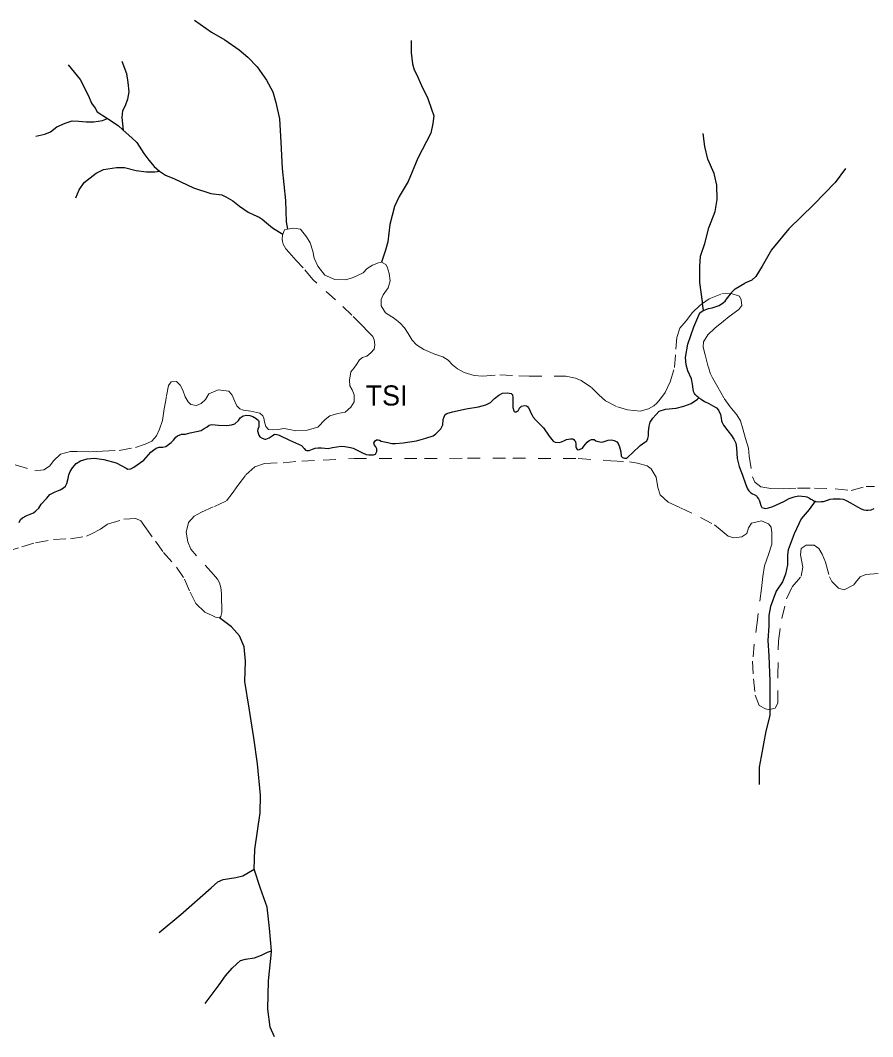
# Model space of a CAD drawing. Extents: x 391.8 to 446, y 8452 to 8507.5.
# Drawn here: x 410.75 to 417.52, y 8495.53 to 8503.6 of the extents above; entities that cross this region are included whole.
import ezdxf
from ezdxf.enums import TextEntityAlignment as Align

# ---------------------------------------------------------------- set-up
doc = ezdxf.new("R2010")
doc.units = 0
doc.header["$LTSCALE"] = 0.064
doc.linetypes.add('LONG_DASHED', pattern=[7.5, 6, -1.5])
doc.linetypes.add('SHORT_DASHED', pattern=[2.7, 1.5, -1.2])
for name, color, linetype, lineweight in [('21', 7, 'SHORT_DASHED', 13), ('7', 7, 'Continuous', 25), ('9', 7, 'LONG_DASHED', 25)]:
    doc.layers.add(name, color=color, linetype=linetype, lineweight=lineweight)
doc.layers.add('61', color=7, linetype='Continuous')

msp = doc.modelspace()

# ---------------------------------------------------------------- linework, layer by layer
at = {"layer": '21'}
for points in [[(412.471, 8500.5378), (412.4932, 8500.512), (412.5227, 8500.501), (412.5818, 8500.4936), (412.6519, 8500.4788), (412.6778, 8500.4567), (412.6852, 8500.4383), (412.6888, 8500.4088), (412.6999, 8500.3719), (412.7221, 8500.3498), (412.7516, 8500.3461), (412.7996, 8500.3498), (412.8439, 8500.3572), (412.8919, 8500.3498), (412.9362, 8500.3387), (413.0285, 8500.3424), (413.1134, 8500.3682), (413.1725, 8500.4272), (413.2094, 8500.4567), (413.2722, 8500.4751), (413.3312, 8500.4862), (413.3755, 8500.5268), (413.4014, 8500.5673), (413.4014, 8500.6226), (413.3866, 8500.6632), (413.3682, 8500.6964), (413.3645, 8500.7406), (413.3768, 8500.8061), (413.4027, 8500.8393), (413.4211, 8500.8651), (413.4433, 8500.9019), (413.4691, 8500.9204), (413.5023, 8500.9314), (413.5356, 8500.9572), (413.5614, 8500.9867), (413.5651, 8501.0199), (413.5614, 8501.0605), (413.5503, 8501.0863), (413.5134, 8501.1232), (413.4654, 8501.1748), (413.3842, 8501.2559), (413.255, 8501.3776), (413.0741, 8501.5398), (412.9965, 8501.632), (412.9412, 8501.691), (412.8858, 8501.7537), (412.8599, 8501.7832), (412.8378, 8501.82), (412.8341, 8501.8422), (412.8304, 8501.8606), (412.833, 8501.8925), (412.833, 8501.8926), (412.8359, 8501.9004)], [(412.8359, 8501.9004), (412.8481, 8501.9334), (412.8727, 8501.9382)], [(412.8727, 8501.9382), (412.9239, 8501.9482), (412.9747, 8501.9388), (413.0222, 8501.8794), (413.0519, 8501.8311), (413.0741, 8501.7647), (413.0852, 8501.7094), (413.1147, 8501.6467), (413.1701, 8501.573), (413.2476, 8501.5398), (413.3362, 8501.5361), (413.3953, 8501.5546), (413.4728, 8501.5914), (413.506, 8501.6283), (413.5466, 8501.6541), (413.5946, 8501.6725), (413.6204, 8501.677)], [(413.6204, 8501.677), (413.6537, 8501.6578), (413.6648, 8501.6394), (413.6796, 8501.5877), (413.6869, 8501.5288), (413.6722, 8501.4734), (413.6316, 8501.4181), (413.6168, 8501.3813), (413.6168, 8501.3296), (413.65, 8501.2743), (413.7239, 8501.2301), (413.7682, 8501.1932), (413.8014, 8501.1564), (413.8309, 8501.1121), (413.8642, 8501.0568), (413.8974, 8501.0199), (413.9565, 8500.9831), (414.0502, 8500.9444), (414.1056, 8500.9259), (414.1499, 8500.9001), (414.1831, 8500.8632), (414.2237, 8500.8301), (414.2754, 8500.8006), (414.3566, 8500.7784), (414.4231, 8500.7711), (414.5597, 8500.7821), (414.711, 8500.7748)], [(416.1704, 8501.3483), (416.2232, 8501.3851), (416.3229, 8501.4256), (416.3948, 8501.4292)], [(416.3948, 8501.4292), (416.3967, 8501.4293), (416.4632, 8501.4072), (416.4779, 8501.3777), (416.4816, 8501.3335), (416.4595, 8501.3003), (416.3819, 8501.245), (416.3376, 8501.2081), (416.2675, 8501.1528), (416.2121, 8501.1012), (416.1789, 8501.0459), (416.1752, 8501.0016), (416.19, 8500.9426), (416.2164, 8500.8445), (416.2311, 8500.7966), (416.2496, 8500.7597), (416.2902, 8500.686), (416.3419, 8500.5938), (416.3899, 8500.5274), (416.4416, 8500.4647), (416.4711, 8500.4168), (416.4896, 8500.3541), (416.5117, 8500.2767), (416.5339, 8500.1993), (416.5412, 8500.1366), (416.5676, 8499.9719), (416.586, 8499.9314), (416.634, 8499.8945), (416.7115, 8499.8797), (416.8112, 8499.8761), (416.9257, 8499.8834), (417.0586, 8499.8834), (417.2247, 8499.8761), (417.3502, 8499.865), (417.4697, 8499.8953), (417.5362, 8499.8953)], [(415.346, 8500.6236), (415.3977, 8500.5756), (415.4937, 8500.5277), (415.575, 8500.5056), (415.6746, 8500.4945), (415.7411, 8500.513), (415.7838, 8500.5358), (415.8059, 8500.558), (415.8354, 8500.5911), (415.8724, 8500.6428), (415.913, 8500.7276), (415.9462, 8500.8419), (415.9573, 8500.9857), (415.9647, 8501.0779), (415.9906, 8501.1528), (416.0386, 8501.2118), (416.0903, 8501.2782), (416.1493, 8501.3335), (416.1704, 8501.3483)], [(414.711, 8500.7748), (414.7923, 8500.7711), (415.0839, 8500.7711), (415.1615, 8500.7563), (415.2058, 8500.7379), (415.2907, 8500.6789), (415.346, 8500.6236)], [(410.7101, 8500.0678), (410.8651, 8500.0191), (410.937, 8500.0272), (410.9821, 8500.0572), (411.0168, 8500.1011), (411.0684, 8500.1527), (411.1497, 8500.1748), (411.2013, 8500.1748), (411.3066, 8500.172), (411.4026, 8500.1757), (411.5355, 8500.1831), (411.6647, 8500.2052), (411.7422, 8500.231), (411.7939, 8500.2568), (411.8308, 8500.2974), (411.8568, 8500.3509), (411.879, 8500.421), (411.8937, 8500.5131), (411.9122, 8500.6164), (411.9269, 8500.6975), (411.9491, 8500.727), (411.9897, 8500.7307), (412.0192, 8500.7012), (412.0414, 8500.6606), (412.0599, 8500.609), (412.082, 8500.5684), (412.1042, 8500.5463), (412.1485, 8500.539), (412.1854, 8500.5537), (412.2223, 8500.5869)], [(412.2223, 8500.5869), (412.2481, 8500.6311), (412.322, 8500.6643), (412.4069, 8500.6533), (412.4327, 8500.6201), (412.4549, 8500.5721), (412.471, 8500.5378)], [(412.3323, 8498.8529), (412.3427, 8498.8643), (412.3502, 8498.8943), (412.3502, 8498.9411), (412.3483, 8498.9955), (412.3483, 8499.0442), (412.3427, 8499.0947), (412.3314, 8499.1303), (412.3164, 8499.1603), (412.2845, 8499.1978), (412.1506, 8499.3464), (412.1056, 8499.3978), (412.0799, 8499.4556), (412.067, 8499.5326), (412.0863, 8499.6097), (412.1313, 8499.661), (412.1892, 8499.6931), (412.292, 8499.7381), (412.3884, 8499.783), (412.4334, 8499.8408), (412.4784, 8499.905), (412.5427, 8499.9884), (412.6134, 8500.0526), (412.6906, 8500.0783), (412.8384, 8500.0847), (412.9863, 8500.0976), (413.1568, 8500.1054), (413.4011, 8500.1183), (413.9603, 8500.1183), (414.3039, 8500.1203), (414.6637, 8500.1203), (415.1817, 8500.1183), (415.4416, 8500.0994), (415.5894, 8500.093), (415.6537, 8500.0801), (415.7308, 8500.0609), (415.763, 8500.0352), (415.8015, 8499.971), (415.8144, 8499.8875), (415.8337, 8499.8298), (415.898, 8499.772), (415.9944, 8499.727), (416.1551, 8499.65), (416.2644, 8499.5922), (416.3094, 8499.5537), (416.3737, 8499.5023), (416.4187, 8499.4895), (416.4829, 8499.4959), (416.5215, 8499.5216), (416.5344, 8499.5665), (416.5601, 8499.6051), (416.6372, 8499.6243), (416.6951, 8499.5986), (416.7144, 8499.573), (416.7208, 8499.528), (416.7208, 8499.4381), (416.6951, 8499.3547), (416.6629, 8499.2648), (416.6501, 8499.1813), (416.6372, 8499.085), (416.6065, 8498.8362), (416.5808, 8498.6436), (416.5679, 8498.5088), (416.5743, 8498.3675), (416.5872, 8498.2391)], [(410.6399, 8499.3785), (410.7621, 8499.4171), (410.8713, 8499.4492), (411.0128, 8499.4748), (411.1478, 8499.4813), (411.2763, 8499.5005), (411.3149, 8499.5198), (411.3856, 8499.5583), (411.4435, 8499.5968), (411.572, 8499.6353), (411.6685, 8499.6418), (411.707, 8499.6225), (411.7392, 8499.5776), (411.8227, 8499.462), (411.887, 8499.3721), (411.9899, 8499.2566), (412.0542, 8499.1603), (412.0992, 8499.0575), (412.1442, 8498.9677), (412.2149, 8498.897), (412.2727, 8498.8714), (412.3052, 8498.8568), (412.3323, 8498.8529)], [(416.7672, 8498.1749), (416.7672, 8498.3996), (416.7736, 8498.6693), (416.7993, 8498.849), (416.8379, 8499.0031), (416.8829, 8499.0994), (416.9536, 8499.1829), (416.9666, 8499.2558), (416.9473, 8499.3521), (416.9537, 8499.4035), (416.9923, 8499.4292), (417.0566, 8499.4292), (417.0951, 8499.4035), (417.1209, 8499.3586), (417.1466, 8499.2944), (417.1787, 8499.1788), (417.198, 8499.1403), (417.2494, 8499.0889), (417.2944, 8499.0761), (417.3716, 8499.1146), (417.3844, 8499.1339), (417.423, 8499.1788), (417.468, 8499.1981), (417.5644, 8499.2045)], [(416.5872, 8498.2391), (416.6193, 8498.1557), (416.6708, 8498.13), (416.7029, 8498.1236), (416.7051, 8498.1242)], [(416.7051, 8498.1242), (416.7479, 8498.1364), (416.7672, 8498.1749)]]:
    msp.add_lwpolyline(points, dxfattribs=at)
at = {"layer": '7'}
for points in [[(416.3948, 8501.4292), (416.3986, 8501.4349), (416.4284, 8501.4647), (416.5067, 8501.5093)], [(416.1769, 8501.2941), (416.2161, 8501.3084), (416.2459, 8501.3158), (416.3018, 8501.3344), (416.3353, 8501.3568), (416.3502, 8501.3679), (416.3688, 8501.394), (416.3837, 8501.4126), (416.3948, 8501.4292)], [(416.1417, 8500.6005), (416.1286, 8500.6118), (416.1182, 8500.6192), (416.1123, 8500.6266), (416.1049, 8500.6355), (416.099, 8500.6503), (416.0945, 8500.668), (416.0895, 8500.7095), (416.082, 8500.7504), (416.0522, 8500.8136), (416.0411, 8500.862), (416.0336, 8500.9215), (416.0522, 8501.0257), (416.1007, 8501.1633), (416.1491, 8501.2749), (416.1751, 8501.2935), (416.1769, 8501.2941)], [(413.0167, 8500.1853), (413.0263, 8500.1829), (413.0455, 8500.1829), (413.0719, 8500.1925), (413.0911, 8500.1997), (413.1151, 8500.2021), (413.1415, 8500.2021), (413.1703, 8500.1997), (413.1967, 8500.1973), (413.2303, 8500.2069), (413.2639, 8500.2117), (413.2999, 8500.2165), (413.3287, 8500.2141), (413.3719, 8500.2069), (413.3935, 8500.1997), (413.4319, 8500.1829), (413.4679, 8500.1637), (413.4967, 8500.1494), (413.5183, 8500.147), (413.5566, 8500.147), (413.571, 8500.1518), (413.583, 8500.1733), (413.583, 8500.1949), (413.5734, 8500.2117), (413.5638, 8500.2237), (413.559, 8500.2428), (413.5686, 8500.2596), (413.5806, 8500.2668), (413.5926, 8500.2668), (413.6046, 8500.2644), (413.6166, 8500.2572), (413.6707, 8500.2453), (413.7019, 8500.2381), (413.7306, 8500.2381), (413.7906, 8500.2429), (413.8962, 8500.2596), (413.9706, 8500.2788), (414.0306, 8500.298), (414.0498, 8500.3148), (414.0906, 8500.3531), (414.1074, 8500.3866), (414.1098, 8500.4274), (414.1175, 8500.4502), (414.1247, 8500.4669), (414.1391, 8500.4765), (414.1847, 8500.4885), (414.2927, 8500.5125), (414.3911, 8500.5293), (414.4487, 8500.5436), (414.4847, 8500.5628), (414.5159, 8500.594), (414.5519, 8500.6203), (414.5807, 8500.6371), (414.6167, 8500.6395), (414.6503, 8500.6347), (414.6599, 8500.6227), (414.6623, 8500.6036), (414.6623, 8500.5245), (414.6695, 8500.4981), (414.6743, 8500.4909), (414.6791, 8500.4885), (414.6887, 8500.4885), (414.6983, 8500.4933), (414.7055, 8500.4981), (414.7103, 8500.5077), (414.7175, 8500.5221), (414.7271, 8500.5293), (414.7318, 8500.5341), (414.7558, 8500.5388), (414.7702, 8500.5364), (414.7798, 8500.5317), (414.787, 8500.5197), (414.7966, 8500.5029), (414.8038, 8500.4861), (414.8158, 8500.4622), (414.8254, 8500.4454), (414.8446, 8500.4238), (414.907, 8500.3615), (414.9526, 8500.2968), (414.9727, 8500.2693), (414.9822, 8500.2549), (414.999, 8500.2477), (415.0302, 8500.2453), (415.0494, 8500.2501), (415.0734, 8500.2621), (415.0902, 8500.2693), (415.1214, 8500.2741), (415.1382, 8500.2741), (415.1478, 8500.2693), (415.1526, 8500.2621), (415.1598, 8500.2525), (415.1622, 8500.2334), (415.1646, 8500.2118), (415.167, 8500.2022), (415.1742, 8500.1902)], [(415.2534, 8500.2477), (415.2702, 8500.2621), (415.287, 8500.2693), (415.3086, 8500.2693), (415.323, 8500.2597), (415.3446, 8500.2525), (415.3638, 8500.2477), (415.3806, 8500.2501), (415.4046, 8500.2597), (415.4214, 8500.2645), (415.4454, 8500.2669), (415.467, 8500.2621), (415.4886, 8500.2501), (415.5006, 8500.2382), (415.5102, 8500.2118), (415.5198, 8500.1711), (415.5246, 8500.1375), (415.5342, 8500.1255), (415.551, 8500.1207), (415.5678, 8500.1207), (415.5798, 8500.1303), (415.6134, 8500.1639), (415.6734, 8500.2214), (415.7118, 8500.2477), (415.7286, 8500.2573), (415.7358, 8500.2765), (415.7406, 8500.2981), (415.7406, 8500.3292), (415.7454, 8500.3748), (415.755, 8500.4059), (415.7742, 8500.4395), (415.7982, 8500.4658), (415.8258, 8500.4951), (415.8762, 8500.5095), (415.9602, 8500.5167), (416.0202, 8500.5335), (416.0801, 8500.555), (416.1305, 8500.5886), (416.1417, 8500.6005)], [(416.1417, 8500.6005), (416.1583, 8500.5881), (416.1849, 8500.5703), (416.219, 8500.5541), (416.2576, 8500.5348), (416.2798, 8500.52), (416.2976, 8500.5008), (416.3139, 8500.4682), (416.3186, 8500.4373), (416.3201, 8500.4181), (416.326, 8500.4033), (416.3378, 8500.3826), (416.3705, 8500.3382), (416.4001, 8500.2997), (416.4194, 8500.273), (416.4268, 8500.2553), (416.4342, 8500.2405), (416.4401, 8500.202), (416.4416, 8500.1591), (416.446, 8500.1191), (416.4598, 8500.0547), (416.4865, 8499.9852), (416.5117, 8499.9171), (416.5265, 8499.8771), (416.5369, 8499.8623), (416.5517, 8499.849), (416.568, 8499.8386), (416.5814, 8499.8312), (416.5977, 8499.8209), (416.6051, 8499.812), (416.6155, 8499.7987), (416.6229, 8499.7809), (416.6273, 8499.7631), (416.6332, 8499.7439), (416.6421, 8499.7291), (416.6584, 8499.7232), (416.6718, 8499.7217), (416.694, 8499.7276), (416.7281, 8499.738), (416.8155, 8499.7765), (416.8585, 8499.8001), (416.8985, 8499.8135), (416.9326, 8499.8209), (416.9842, 8499.8171), (416.9998, 8499.8129), (417.0098, 8499.8086), (417.0198, 8499.8029), (417.0297, 8499.7958), (417.0425, 8499.7901), (417.0553, 8499.783), (417.0655, 8499.7789)], [(410.7409, 8499.6112), (410.7505, 8499.6328), (410.7673, 8499.6472), (410.8009, 8499.6663), (410.8537, 8499.6879), (410.8729, 8499.7023), (410.8969, 8499.7239), (410.9161, 8499.755), (410.9593, 8499.8029), (410.9833, 8499.8317), (411.0265, 8499.8533), (411.0673, 8499.8701), (411.0936, 8499.8844), (411.108, 8499.8988), (411.12, 8499.9204), (411.1296, 8499.9587), (411.1344, 8499.9899), (411.1464, 8500.0138), (411.1656, 8500.045), (411.1926, 8500.0773), (411.2286, 8500.0989), (411.2814, 8500.1157), (411.339, 8500.1205), (411.4134, 8500.1109), (411.5118, 8500.0845), (411.555, 8500.0605), (411.591, 8500.0414), (411.603, 8500.0342), (411.627, 8500.0366), (411.651, 8500.0486), (411.7302, 8500.1061), (411.7878, 8500.1684), (411.8099, 8500.1882), (411.8291, 8500.2001), (411.8531, 8500.2073), (411.8819, 8500.2073), (411.9059, 8500.2145), (411.9275, 8500.2289), (411.9491, 8500.2457), (411.9659, 8500.2649), (411.9851, 8500.2864), (411.9995, 8500.2984), (412.0307, 8500.3104), (412.0619, 8500.3128), (412.0979, 8500.3224), (412.1483, 8500.332), (412.1867, 8500.3415), (412.2107, 8500.3559), (412.2333, 8500.3704), (412.2501, 8500.3824), (412.2717, 8500.3872), (412.3245, 8500.3824), (412.3893, 8500.38), (412.4277, 8500.3848), (412.4541, 8500.3944), (412.4829, 8500.4207), (412.4973, 8500.4423), (412.5213, 8500.4567), (412.5501, 8500.4615), (412.5741, 8500.4591), (412.5981, 8500.4519), (412.6244, 8500.4351), (412.6412, 8500.4207), (412.646, 8500.4136), (412.646, 8500.3704), (412.6364, 8500.3512), (412.634, 8500.3369), (412.6436, 8500.3033), (412.6532, 8500.2913), (412.67, 8500.2793), (412.6916, 8500.2722), (412.7012, 8500.2722), (412.7276, 8500.2817), (412.7516, 8500.2985), (412.7684, 8500.3105)], [(412.7684, 8500.3105), (412.7876, 8500.3081), (412.8068, 8500.3033), (412.8884, 8500.265), (412.9844, 8500.2218), (413.0047, 8500.1973), (413.0167, 8500.1853)], [(415.1742, 8500.1902), (415.1862, 8500.1878), (415.1982, 8500.1926), (415.215, 8500.1998), (415.227, 8500.2166), (415.2414, 8500.2334), (415.2534, 8500.2477)], [(417.0655, 8499.7789), (417.0177, 8499.7139), (416.9533, 8499.6397), (416.8988, 8499.5209), (416.8492, 8499.3923), (416.8443, 8499.3527), (416.8443, 8499.2736), (416.8294, 8499.1994), (416.8047, 8499.14), (416.7551, 8499.0658), (416.7105, 8498.9421), (416.6957, 8498.8728), (416.6974, 8498.7902), (416.6896, 8498.6741), (416.6974, 8498.5503), (416.7051, 8498.3491), (416.7051, 8498.1242)], [(417.0655, 8499.7789), (417.0696, 8499.7773), (417.0895, 8499.7731), (417.1122, 8499.7759), (417.1322, 8499.7773), (417.1478, 8499.783), (417.162, 8499.7873), (417.1834, 8499.7944), (417.209, 8499.7972), (417.2645, 8499.7972), (417.2872, 8499.7944), (417.31, 8499.7859), (417.3456, 8499.7674), (417.4011, 8499.7347), (417.4302, 8499.7177), (417.4502, 8499.7106), (417.4701, 8499.7078), (417.4872, 8499.7078), (417.5085, 8499.7106), (417.5341, 8499.7206)], [(416.7051, 8498.1242), (416.7051, 8498.0782), (416.6741, 8497.9544), (416.6354, 8497.7532), (416.6199, 8497.668), (416.6199, 8497.5287)]]:
    msp.add_lwpolyline(points, dxfattribs=at)
at = {"layer": '9'}
msp.add_line((416.1769, 8501.2941), (416.1704, 8501.3483), dxfattribs=at)
for points in [[(412.1329, 8503.5976), (412.27, 8503.5028), (412.3754, 8503.4431), (412.4879, 8503.3624), (412.5582, 8503.3062), (412.632, 8503.229), (412.7058, 8503.1237), (412.755, 8503.0289), (412.7803, 8502.9464), (412.8084, 8502.8165), (412.819, 8502.6304), (412.8295, 8502.4198), (412.8576, 8502.1658), (412.8611, 8501.9973), (412.8727, 8501.9382)], [(413.8543, 8503.4386), (413.8543, 8503.3428), (413.8663, 8503.2529), (413.8783, 8503.205), (413.8963, 8503.169), (413.9383, 8503.0791), (413.9863, 8502.9773), (414.0163, 8502.8934), (414.0343, 8502.8395), (414.0283, 8502.7795), (414.0103, 8502.7016), (413.9083, 8502.5039), (413.8303, 8502.3182), (413.7584, 8502.1983), (413.7224, 8502.1204), (413.6864, 8501.9766), (413.6684, 8501.8388), (413.6504, 8501.7729), (413.6204, 8501.677)], [(411.5555, 8503.2727), (411.5942, 8503.1744), (411.6048, 8503.1042), (411.6118, 8503.0305), (411.6012, 8502.9708), (411.5837, 8502.9182), (411.5626, 8502.8796), (411.5555, 8502.8269), (411.5661, 8502.7251)], [(411.1302, 8503.2447), (411.2251, 8503.1288), (411.2919, 8502.9989), (411.3165, 8502.9392), (411.3446, 8502.9006), (411.36, 8502.8702), (411.4415, 8502.8187)], [(410.8719, 8502.6779), (410.9452, 8502.6948), (410.9904, 8502.7117), (411.0404, 8502.7506), (411.1051, 8502.7809), (411.1621, 8502.7988), (411.2159, 8502.7962), (411.2723, 8502.7905), (411.3343, 8502.7905), (411.402, 8502.8018), (411.4415, 8502.8187)], [(411.4415, 8502.8187), (411.5274, 8502.7637), (411.5661, 8502.7251)], [(411.5661, 8502.7251), (411.6364, 8502.6654), (411.6751, 8502.6268), (411.7313, 8502.5391), (411.77, 8502.4864), (411.8121, 8502.4373), (411.8543, 8502.3986)], [(416.1704, 8501.3483), (416.1689, 8501.3611), (416.1494, 8501.516), (416.1494, 8501.6453), (416.1534, 8501.7236), (416.1886, 8501.8254), (416.22, 8501.9507), (416.271, 8502.08), (416.2867, 8502.174), (416.2828, 8502.2875), (416.2631, 8502.3815), (416.2122, 8502.4951), (416.1888, 8502.5945), (416.1757, 8502.6986)], [(411.19, 8502.188), (411.2181, 8502.2512), (411.2568, 8502.3109), (411.306, 8502.346), (411.3517, 8502.3846), (411.4114, 8502.4127), (411.5134, 8502.4302), (411.5766, 8502.4302), (411.6715, 8502.4057), (411.7524, 8502.3951), (411.8192, 8502.3951), (411.8543, 8502.3986)], [(411.8543, 8502.3986), (411.9035, 8502.367), (411.9738, 8502.339), (412.125, 8502.2688), (412.2635, 8502.2214), (412.3514, 8502.2108), (412.383, 8502.1968), (412.4392, 8502.1652), (412.492, 8502.1231), (412.5588, 8502.0739), (412.6044, 8502.0529), (412.6466, 8502.0353), (412.6712, 8502.0178), (412.7064, 8501.9897), (412.7521, 8501.9511), (412.8083, 8501.916), (412.8359, 8501.9004)], [(417.3065, 8502.4203), (417.2241, 8502.3106), (417.0555, 8502.1344), (416.8555, 8501.9425), (416.7183, 8501.7741), (416.6438, 8501.6449), (416.5928, 8501.5626), (416.5614, 8501.5352), (416.5067, 8501.5093)], [(412.6069, 8496.8575), (412.6133, 8497.0142), (412.6547, 8497.3036), (412.6578, 8497.4447), (412.6341, 8497.6927), (412.6046, 8497.8994), (412.5691, 8498.1357), (412.5336, 8498.3483), (412.5395, 8498.5077), (412.5275, 8498.6225), (412.492, 8498.7111), (412.4269, 8498.782), (412.3323, 8498.8529)], [(411.8531, 8496.3554), (412.0246, 8496.4972), (412.267, 8496.7098), (412.3202, 8496.757), (412.3616, 8496.7747), (412.4622, 8496.7924), (412.517, 8496.8045), (412.5493, 8496.8229), (412.6069, 8496.8575)], [(412.7454, 8496.2086), (412.7284, 8496.3896), (412.7107, 8496.5549), (412.6575, 8496.7026), (412.6069, 8496.8575)], [(412.2185, 8495.7919), (412.33, 8495.9379), (412.3793, 8496.0109), (412.4341, 8496.0712), (412.4707, 8496.1059), (412.4999, 8496.1314), (412.5401, 8496.1424), (412.6096, 8496.1533), (412.6662, 8496.1752), (412.7138, 8496.1971), (412.7454, 8496.2086)], [(412.7698, 8495.5273), (412.7344, 8495.6041), (412.7166, 8495.7458), (412.7225, 8495.9702), (412.7462, 8496.2006), (412.7454, 8496.2086)]]:
    msp.add_lwpolyline(points, dxfattribs=at)

# ---------------------------------------------------------------- texts
at = {"layer": '61'}
msp.add_text('TSI', height=0.16, dxfattribs=at).set_placement((413.6597, 8500.5388), align=Align.CENTER)

doc.saveas('drawing.dxf')
